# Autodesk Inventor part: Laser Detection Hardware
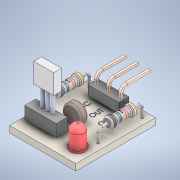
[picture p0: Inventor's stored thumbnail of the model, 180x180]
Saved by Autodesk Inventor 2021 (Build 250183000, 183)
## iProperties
Created: 2020-03
Part Number: Laser Detection Hardware
Material: Generic
Document SubType Name: Modeling
Designer: alolo
Density: 1 g/cm^3
Appearance: Default
Sending System: SolidWorks 2019
Last Author: Sammy Meschino
Last Saved: 2020-03-13
Author: alolo
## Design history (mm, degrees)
feature "Laser Receiver-1-solid1"
feature "Laser Receiver-1-solid2"
feature "Laser Receiver-1-solid3"
feature "Laser Receiver-1-solid4"
feature "Laser Receiver-1-solid5"
feature "Laser Receiver-1-solid6"
feature "Resistor 10K Ohm-1-solid1"
feature "Resistor 10K Ohm-2-solid1"
node "Direct Edit1"
node "Direct Edit2"
delete_face "Delete Face1"
sketch "Sketch1"
  geometry: L1 (0, 0)-(0, -1.778) reference; L2 (4.572, 0)-(0, 0) reference; C1 r 0.4 at (1.086, -0.889); C2 r 0.4 at (2.286, -0.889); C3 r 0.4 at (3.486, -0.889); 3 further points
  constraints: 3 centre point, 3 horizontal alignment, 2 equal radius, 2 midpoint, 1 vertical alignment
  dimensions: "d6" = 0.8 diameter of C2; "d7" = 1.2 distance of C2.centre C1.centre; "d8" = 1.2 distance of C3.centre C2.centre
node "Direct Edit4"
extrude "Extrusion1" join sketch "Sketch1" stored distance "d9" = 1.2 (= d8); taper "d10" = 0 deg
body "Solid1"
body "Solid2"
body "Solid3"
body "Solid4"
body "Solid5"
body "Solid6"
body "Solid7"
body "Solid8"
feature "Delete1"
move_body "Move1" dims "d0" = 0, "d1" = 4.7752, "d2" = 15.875
move_body "Move2" dims "d4" = -1.588
other parameters: "d3" = 0, "d5" = 0
